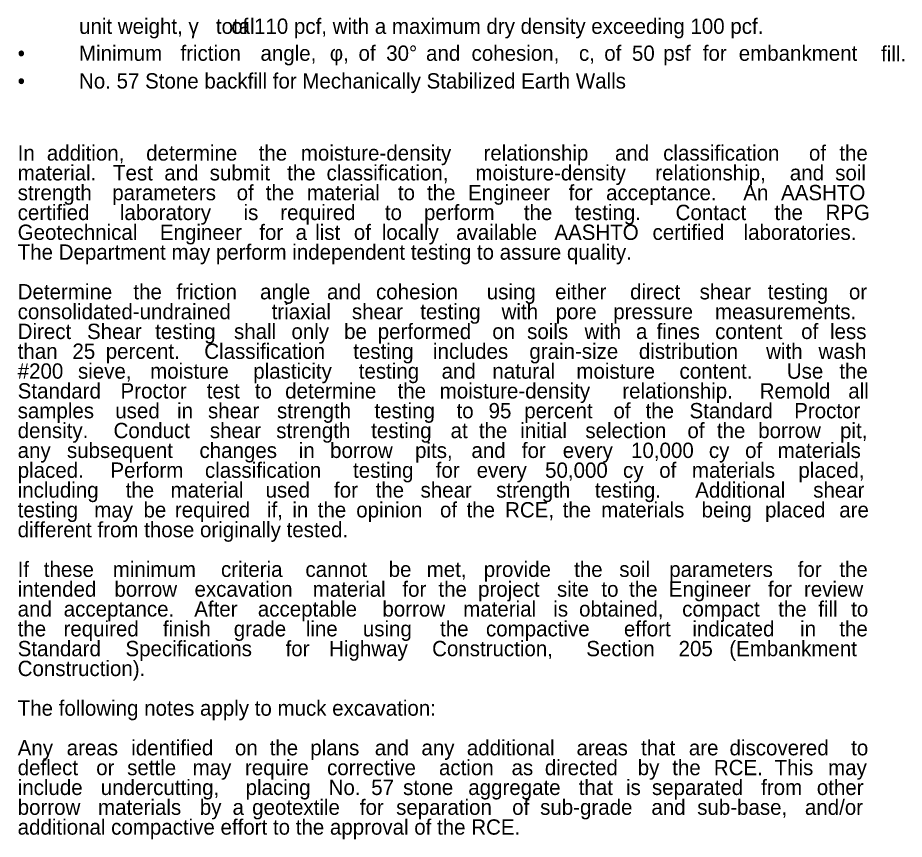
# Model space of a CAD drawing. Extents: x 4804 to 5434, y 4929 to 5221.
# Drawn here: x 4804.3 to 4884.3, y 5000.6 to 5074.9 of the extents above; entities that cross this region are included whole.
import ezdxf

# ---------------------------------------------------------------- set-up
doc = ezdxf.new("R2010")
doc.units = 0
doc.layers.add('RD_TX_RoadID', color=7, linetype='Continuous')

msp = doc.modelspace()

# ---------------------------------------------------------------- texts
at = {"layer": 'RD_TX_RoadID'}
for s, height, p in [('unit weight, γ', 1.3845, (4809.795, 5073.414)), ('total ', 1.3845, (4822.151, 5073.414)), ('of 110 pcf, with a maximum dry density exceeding 100 pcf. ', 1.3845, (4823.537, 5073.414)), ('Minimum ', 1.3845, (4809.789, 5070.976)), ('friction ', 1.3845, (4818.951, 5070.976)), ('angle, ', 1.3845, (4826.177, 5070.976)), ('φ, ', 1.3845, (4832.439, 5070.976)), ('of ', 1.3845, (4835.032, 5070.976)), ('30° ', 1.3845, (4837.531, 5070.976)), ('and ', 1.3845, (4841.128, 5070.976)), ('cohesion, ', 1.3845, (4845.24, 5070.976)), ('c, ', 1.3845, (4854.94, 5070.976)), ('of ', 1.3845, (4857.225, 5070.976)), ('50 ', 1.3845, (4859.724, 5070.976)), ('psf ', 1.3845, (4862.547, 5070.976)), ('for ', 1.3845, (4866.121, 5070.976)), ('embankment ', 1.3845, (4869.372, 5070.976)), ('fill.', 1.3845, (4882.224, 5070.921)), ('•', 1.384, (4804.251, 5070.976)), ('No. 57 Stone backfill for Mechanically Stabilized Earth Walls', 1.3845, (4809.789, 5068.47)), ('•', 1.384, (4804.251, 5068.47)), ('In ', 1.3845, (4804.251, 5061.958)), ('addition, ', 1.3845, (4806.883, 5061.958)), ('determine ', 1.3845, (4815.854, 5061.958)), ('the ', 1.3845, (4826.011, 5061.958)), ('moisture-density ', 1.3845, (4829.825, 5061.958)), ('relationship ', 1.3845, (4846.32, 5061.958)), ('and ', 1.3845, (4858.194, 5061.958)), ('classification ', 1.3845, (4862.547, 5061.958)), ('of ', 1.3845, (4875.711, 5061.958)), ('the ', 1.3845, (4878.45, 5061.958)), ('material. ', 1.3845, (4804.251, 5060.166)), ('and ', 1.3845, (4817.494, 5060.166)), ('submit ', 1.3845, (4821.59, 5060.166)), ('the ', 1.3845, (4828.587, 5060.166)), ('classification, ', 1.3845, (4832.145, 5060.166)), ('moisture-density ', 1.3845, (4845.59, 5060.166)), ('relationship, ', 1.3845, (4861.829, 5060.166)), ('and ', 1.3845, (4873.984, 5060.166)), ('soil ', 1.3845, (4878.08, 5060.166)), ('Test ', 1.3845, (4812.861, 5060.166)), ('strength ', 1.3845, (4804.251, 5058.374)), ('parameters ', 1.3845, (4812.793, 5058.374)), ('of ', 1.3845, (4824.025, 5058.374)), ('the ', 1.3845, (4826.657, 5058.374)), ('material ', 1.3845, (4830.363, 5058.374)), ('to ', 1.3845, (4838.585, 5058.374)), ('the ', 1.3845, (4841.216, 5058.374)), ('Engineer ', 1.3845, (4844.923, 5058.374)), ('for ', 1.3845, (4854.005, 5058.374)), ('acceptance. ', 1.3845, (4857.389, 5058.374)), (' An ', 1.3845, (4869.266, 5058.374)), ('AASHTO ', 1.3845, (4873.188, 5058.374)), ('certified ', 1.3845, (4804.251, 5056.582)), ('laboratory ', 1.3845, (4813.48, 5056.582)), ('is ', 1.3845, (4824.645, 5056.582)), ('required ', 1.3845, (4827.965, 5056.582)), ('to ', 1.3845, (4837.411, 5056.582)), ('perform ', 1.3845, (4840.944, 5056.582)), ('the ', 1.3845, (4849.96, 5056.582)), ('testing. ', 1.3845, (4854.568, 5056.582)), (' Contact ', 1.3845, (4863.152, 5056.582)), ('the ', 1.3845, (4872.596, 5056.582)), ('RPG ', 1.3845, (4877.204, 5056.582)), ('Geotechnical ', 1.3845, (4804.251, 5054.79)), ('Engineer ', 1.3845, (4817.094, 5054.79)), ('for ', 1.3845, (4826.069, 5054.79)), ('list ', 1.3845, (4831.118, 5054.79)), ('of ', 1.3845, (4834.61, 5054.79)), ('locally ', 1.3845, (4837.133, 5054.79)), ('available ', 1.3845, (4843.851, 5054.79)), ('AASHTO ', 1.3845, (4852.719, 5054.79)), ('certified ', 1.3845, (4861.586, 5054.79)), ('laboratories. ', 1.3845, (4869.806, 5054.79)), ('a ', 1.3845, (4829.345, 5054.79)), ('The Department may perform independent testing to assure quality. ', 1.3845, (4804.251, 5052.998)), ('Determine ', 1.3845, (4804.251, 5049.415)), ('the ', 1.3845, (4814.701, 5049.415)), ('friction ', 1.3845, (4818.594, 5049.415)), ('angle ', 1.3845, (4826.14, 5049.415)), ('and ', 1.3845, (4832.183, 5049.415)), ('cohesion ', 1.3845, (4836.615, 5049.415)), (' using ', 1.3845, (4846.097, 5049.415)), ('either ', 1.3845, (4852.785, 5049.415)), (' direct ', 1.3845, (4859.043, 5049.415)), ('shear ', 1.3845, (4865.838, 5049.415)), ('testing ', 1.3845, (4871.99, 5049.415)), ('or ', 1.3845, (4879.321, 5049.415)), ('consolidated-undrained ', 1.3845, (4804.251, 5047.623)), ('triaxial ', 1.3845, (4827.186, 5047.623)), ('shear ', 1.3845, (4834.432, 5047.623)), ('testing ', 1.3845, (4840.605, 5047.623)), ('with ', 1.3845, (4847.956, 5047.623)), ('measurements. ', 1.3845, (4867.223, 5047.623)), ('pore ', 1.3845, (4852.837, 5047.623)), ('pressure ', 1.3845, (4858.041, 5047.623)), ('Direct ', 1.3845, (4804.251, 5045.831)), ('Shear ', 1.3845, (4810.512, 5045.831)), ('testing ', 1.3845, (4816.668, 5045.831)), ('shall ', 1.3845, (4823.787, 5045.831)), ('only ', 1.3845, (4828.974, 5045.831)), ('be ', 1.3845, (4833.73, 5045.831)), ('performed ', 1.3845, (4836.768, 5045.831)), ('soils ', 1.3845, (4850.257, 5045.831)), ('with ', 1.3845, (4855.444, 5045.831)), ('fines ', 1.3845, (4861.947, 5045.831)), ('of ', 1.3845, (4875.005, 5045.831)), ('less ', 1.3845, (4877.61, 5045.831)), ('on ', 1.3845, (4847.113, 5045.831)), ('a ', 1.3845, (4860.092, 5045.831)), ('content ', 1.3845, (4867.241, 5045.831)), ('than ', 1.3845, (4804.251, 5044.039)), ('25 ', 1.3845, (4809.194, 5044.039)), ('percent. ', 1.3845, (4812.204, 5044.039)), (' Classification ', 1.3845, (4820.587, 5044.039)), ('testing ', 1.3845, (4834.557, 5044.039)), ('includes ', 1.3845, (4841.756, 5044.039)), ('grain-size ', 1.3845, (4850.462, 5044.039)), ('distribution ', 1.3845, (4860.35, 5044.039)), ('with ', 1.3845, (4871.846, 5044.039)), ('wash ', 1.3845, (4876.573, 5044.039)), ('#200 ', 1.3845, (4804.251, 5042.247)), ('sieve, ', 1.3845, (4809.696, 5042.247)), ('moisture ', 1.3845, (4816.215, 5042.247)), ('plasticity ', 1.3845, (4825.526, 5042.247)), ('testing ', 1.3845, (4835.052, 5042.247)), ('and ', 1.3845, (4842.535, 5042.247)), ('natural ', 1.3845, (4847.117, 5042.247)), ('moisture ', 1.3845, (4854.709, 5042.247)), ('content. ', 1.3845, (4864.02, 5042.247)), ('  Use ', 1.3845, (4872.685, 5042.247)), ('the ', 1.3845, (4878.45, 5042.247)), ('Standard ', 1.3845, (4804.251, 5040.456)), ('Proctor ', 1.3845, (4813.542, 5040.456)), ('test ', 1.3845, (4821.327, 5040.456)), ('to ', 1.3845, (4825.673, 5040.456)), ('determine ', 1.3845, (4828.406, 5040.456)), ('the ', 1.3845, (4838.557, 5040.456)), ('moisture-density ', 1.3845, (4842.365, 5040.456)), ('relationship. ', 1.3845, (4858.855, 5040.456)), ('Remold ', 1.3845, (4871.261, 5040.456)), ('all ', 1.3845, (4879.262, 5040.456)), ('samples ', 1.3845, (4804.251, 5038.664)), ('used ', 1.3845, (4813.062, 5038.664)), ('in ', 1.3845, (4818.647, 5038.664)), ('shear ', 1.3845, (4821.436, 5038.664)), ('strength ', 1.3845, (4827.667, 5038.664)), ('testing ', 1.3845, (4836.473, 5038.664)), ('95 ', 1.3845, (4846.779, 5038.664)), ('of ', 1.3845, (4858.056, 5038.664)), ('the ', 1.3845, (4860.952, 5038.664)), ('Standard ', 1.3845, (4864.924, 5038.664)), ('Proctor ', 1.3845, (4874.377, 5038.664)), ('to ', 1.3845, (4843.883, 5038.664)), ('percent ', 1.3845, (4850, 5038.664)), ('density. ', 1.3845, (4804.251, 5036.872)), (' Conduct ', 1.3845, (4812.393, 5036.872)), ('shear ', 1.3845, (4821.608, 5036.872)), ('strength ', 1.3845, (4827.602, 5036.872)), ('testing ', 1.3845, (4836.173, 5036.872)), ('at ', 1.3845, (4843.346, 5036.872)), ('the ', 1.3845, (4845.899, 5036.872)), ('initial ', 1.3845, (4849.634, 5036.872)), ('selection ', 1.3845, (4855.517, 5036.872)), ('of ', 1.3845, (4864.735, 5036.872)), ('the ', 1.3845, (4867.394, 5036.872)), ('borrow ', 1.3845, (4871.129, 5036.872)), ('pit, ', 1.3845, (4878.519, 5036.872)), ('any ', 1.3845, (4804.251, 5035.08)), ('subsequent ', 1.3845, (4808.699, 5035.08)), ('changes ', 1.3845, (4820.669, 5035.08)), ('in ', 1.3845, (4829.631, 5035.08)), ('borrow ', 1.3845, (4832.466, 5035.08)), ('pits, ', 1.3845, (4840.137, 5035.08)), ('and ', 1.3845, (4845.228, 5035.08)), ('for ', 1.3845, (4849.782, 5035.08)), ('every ', 1.3845, (4853.476, 5035.08)), ('10,000 ', 1.3845, (4859.645, 5035.08)), ('cy ', 1.3845, (4866.674, 5035.08)), ('of ', 1.3845, (4869.941, 5035.08)), ('materials ', 1.3845, (4872.882, 5035.08)), ('placed. ', 1.3845, (4804.251, 5033.288)), ('Perform ', 1.3845, (4812.624, 5033.288)), ('classification ', 1.3845, (4821.164, 5033.288)), ('testing ', 1.3845, (4834.539, 5033.288)), ('for ', 1.3845, (4842.001, 5033.288)), ('50,000 ', 1.3845, (4851.88, 5033.288)), ('of ', 1.3845, (4862.191, 5033.288)), ('materials ', 1.3845, (4865.14, 5033.288)), ('placed, ', 1.3845, (4874.755, 5033.288)), ('every ', 1.3845, (4845.703, 5033.288)), ('cy ', 1.3845, (4858.917, 5033.288)), ('including ', 1.3845, (4804.251, 5031.497)), ('the ', 1.3845, (4814.003, 5031.497)), ('material ', 1.3845, (4818.06, 5031.497)), ('used ', 1.3845, (4826.633, 5031.497)), (' for ', 1.3845, (4832.303, 5031.497)), ('the ', 1.3845, (4836.575, 5031.497)), ('shear ', 1.3845, (4840.632, 5031.497)), (' strength ', 1.3845, (4846.948, 5031.497)), ('testing. ', 1.3845, (4856.377, 5031.497)), ('  Additional ', 1.3845, (4864.41, 5031.497)), ('shear ', 1.3845, (4876.095, 5031.497)), ('testing ', 1.3845, (4804.251, 5029.705)), ('may ', 1.3845, (4811.166, 5029.705)), ('be ', 1.3845, (4815.613, 5029.705)), ('required ', 1.3845, (4818.447, 5029.705)), ('if, ', 1.3845, (4826.761, 5029.705)), ('in ', 1.3845, (4829.055, 5029.705)), ('the ', 1.3845, (4831.351, 5029.705)), ('opinion ', 1.3845, (4834.828, 5029.705)), ('of ', 1.3845, (4842.388, 5029.705)), ('the ', 1.3845, (4844.79, 5029.705)), ('RCE, ', 1.3845, (4848.267, 5029.705)), ('the ', 1.3845, (4853.465, 5029.705)), ('materials ', 1.3845, (4856.943, 5029.705)), ('being ', 1.3845, (4866.011, 5029.705)), ('placed ', 1.3845, (4871.745, 5029.705)), ('are ', 1.3845, (4878.448, 5029.705)), ('different from those originally tested. ', 1.3845, (4804.251, 5027.913)), ('If ', 1.3845, (4804.251, 5024.329)), ('these ', 1.3845, (4806.609, 5024.329)), ('minimum ', 1.3845, (4812.837, 5024.329)), ('criteria ', 1.3845, (4822.612, 5024.329)), ('cannot ', 1.3845, (4830.238, 5024.329)), ('be ', 1.3845, (4837.755, 5024.329)), ('met, ', 1.3845, (4841.189, 5024.329)), ('provide ', 1.3845, (4846.342, 5024.329)), ('the ', 1.3845, (4854.505, 5024.329)), ('soil ', 1.3845, (4858.583, 5024.329)), ('parameters ', 1.3845, (4863.091, 5024.329)), ('for ', 1.3845, (4874.695, 5024.329)), ('the ', 1.3845, (4878.45, 5024.329)), ('intended ', 1.3845, (4804.251, 5022.537)), ('borrow ', 1.3845, (4812.989, 5022.537)), ('excavation ', 1.3845, (4820.222, 5022.537)), ('material ', 1.3845, (4830.898, 5022.537)), ('for ', 1.3845, (4838.993, 5022.537)), ('the ', 1.3845, (4842.249, 5022.537)), ('project ', 1.3845, (4845.829, 5022.537)), ('site ', 1.3845, (4852.955, 5022.537)), ('the ', 1.3845, (4859.469, 5022.537)), ('Engineer ', 1.3845, (4863.049, 5022.537)), ('for ', 1.3845, (4872.004, 5022.537)), ('review ', 1.3845, (4875.26, 5022.537)), ('to ', 1.3845, (4856.965, 5022.537)), ('and ', 1.3845, (4804.251, 5020.746)), ('acceptance. ', 1.3845, (4808.407, 5020.746)), ('After ', 1.3845, (4820.196, 5020.746)), (' acceptable ', 1.3845, (4825.425, 5020.746)), (' borrow ', 1.3845, (4836.676, 5020.746)), ('material ', 1.3845, (4844.486, 5020.746)), ('is ', 1.3845, (4852.619, 5020.746)), ('obtained, ', 1.3845, (4854.949, 5020.746)), ('compact ', 1.3845, (4864.262, 5020.746)), ('the ', 1.3845, (4872.932, 5020.746)), ('fill ', 1.3845, (4876.55, 5020.746)), ('to ', 1.3845, (4879.522, 5020.746)), ('the ', 1.3845, (4804.251, 5018.954)), ('required ', 1.3845, (4808.391, 5018.954)), ('finish ', 1.3845, (4817.369, 5018.954)), ('grade ', 1.3845, (4823.765, 5018.954)), ('line ', 1.3845, (4830.271, 5018.954)), ('using ', 1.3845, (4835.422, 5018.954)), ('the ', 1.3845, (4842.401, 5018.954)), ('compactive ', 1.3845, (4846.541, 5018.954)), ('effort ', 1.3845, (4859.002, 5018.954)), ('indicated ', 1.3845, (4865.182, 5018.954)), ('in ', 1.3845, (4874.911, 5018.954)), ('the ', 1.3845, (4878.45, 5018.954)), ('Standard ', 1.3845, (4804.251, 5017.162)), ('Specifications ', 1.3845, (4813.984, 5017.162)), ('for ', 1.3845, (4828.446, 5017.162)), ('Highway ', 1.3845, (4832.375, 5017.162)), ('Construction, ', 1.3845, (4841.679, 5017.162)), ('Section ', 1.3845, (4855.6, 5017.162)), ('205 ', 1.3845, (4863.937, 5017.162)), ('(Embankment ', 1.3845, (4868.513, 5017.162)), ('Construction).', 1.3845, (4804.251, 5015.37)), ('The following notes apply to muck excavation:', 1.3845, (4804.251, 5011.786)), ('Any ', 1.3845, (4804.251, 5008.203)), ('identified ', 1.3845, (4814.503, 5008.203)), ('the ', 1.3845, (4827.005, 5008.203)), ('plans ', 1.3845, (4830.678, 5008.203)), ('and ', 1.3845, (4836.501, 5008.203)), ('additional ', 1.3845, (4844.817, 5008.203)), ('that ', 1.3845, (4860.547, 5008.203)), ('discovered ', 1.3845, (4868.539, 5008.203)), ('areas ', 1.3845, (4808.677, 5008.203)), ('on ', 1.3845, (4823.87, 5008.203)), ('any ', 1.3845, (4840.712, 5008.203)), ('areas ', 1.3845, (4854.722, 5008.203)), ('are ', 1.3845, (4864.864, 5008.203)), ('to ', 1.3845, (4879.522, 5008.203)), ('deflect ', 1.3845, (4804.251, 5006.411)), ('or ', 1.3845, (4811.343, 5006.411)), ('settle ', 1.3845, (4814.137, 5006.411)), ('may ', 1.3845, (4820.047, 5006.411)), ('require ', 1.3845, (4824.777, 5006.411)), ('corrective ', 1.3845, (4832.193, 5006.411)), ('action ', 1.3845, (4842.297, 5006.411)), ('as ', 1.3845, (4848.852, 5006.411)), ('directed ', 1.3845, (4851.862, 5006.411)), ('by ', 1.3845, (4860.245, 5006.411)), ('the ', 1.3845, (4863.361, 5006.411)), ('RCE. ', 1.3845, (4867.122, 5006.411)), ('This ', 1.3845, (4872.604, 5006.411)), ('may ', 1.3845, (4877.439, 5006.411)), ('include ', 1.3845, (4804.251, 5004.619)), ('undercutting, ', 1.3845, (4811.75, 5004.619)), ('placing ', 1.3845, (4824.834, 5004.619)), ('No. ', 1.3845, (4832.333, 5004.619)), ('57 ', 1.3845, (4836.178, 5004.619)), ('stone ', 1.3845, (4839.057, 5004.619)), ('aggregate ', 1.3845, (4844.943, 5004.619)), ('that ', 1.3845, (4854.915, 5004.619)), ('is ', 1.3845, (4859.188, 5004.619)), ('separated ', 1.3845, (4861.529, 5004.619)), ('from ', 1.3845, (4871.394, 5004.619)), ('other ', 1.3845, (4876.42, 5004.619)), ('borrow ', 1.3845, (4804.251, 5002.827)), ('materials ', 1.3845, (4811.505, 5002.827)), ('by ', 1.3845, (4820.696, 5002.827)), ('geotextile ', 1.3845, (4825.426, 5002.827)), ('for ', 1.3845, (4835.151, 5002.827)), ('separation ', 1.3845, (4838.428, 5002.827)), ('of ', 1.3845, (4848.907, 5002.827)), ('sub-grade ', 1.3845, (4851.432, 5002.827)), ('and ', 1.3845, (4861.48, 5002.827)), ('sub-base, ', 1.3845, (4865.618, 5002.827)), ('and/or ', 1.3845, (4875.345, 5002.827)), ('a ', 1.3845, (4823.652, 5002.827)), ('additional compactive effort to the approval of the RCE. ', 1.3845, (4804.251, 5001.035))]:
    msp.add_text(s, height=height, dxfattribs=at).set_placement(p)

doc.saveas('drawing.dxf')
